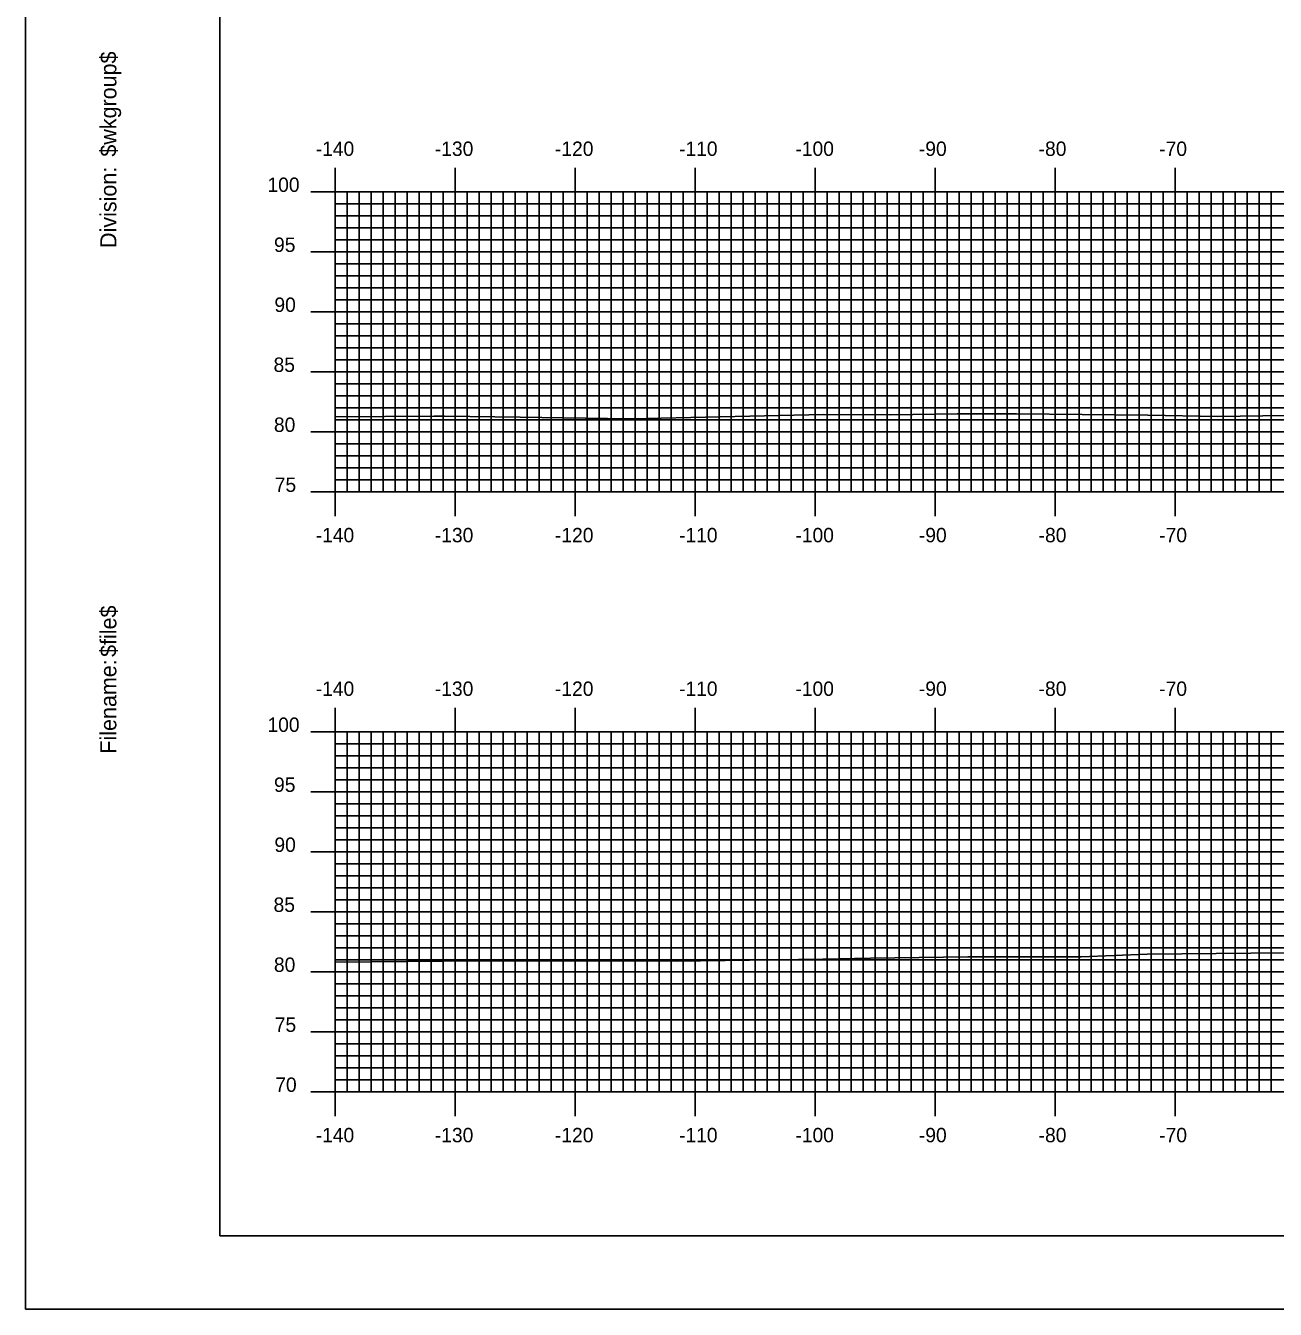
# Model space of a CAD drawing. Extents: x 853723 to 854066, y 364366 to 364586.
# Drawn here: x 853722.9 to 853827.1, y 364365.7 to 364472.6 of the extents above; entities that cross this region are included whole.
import ezdxf

# ---------------------------------------------------------------- set-up
doc = ezdxf.new("R2010")
doc.units = 0
for name, color, linetype in [('BORDER', 7, 'Continuous'), ('H_V ANNOTATION', 7, 'Continuous'), ('MAJOR', 7, 'Continuous'), ('MINOR', 7, 'Continuous'), ('PLOT BOUNDARY', 7, 'Continuous'), ('S_Roadway_Centerline', 7, 'Continuous')]:
    doc.layers.add(name, color=color, linetype=linetype)

msp = doc.modelspace()

# ---------------------------------------------------------------- linework, layer by layer
at = {"layer": 'BORDER'}
msp.add_lwpolyline([(853739.12, 364371.79), (854059.12, 364371.79), (854059.12, 364581.79), (853739.12, 364581.79)], close=True, dxfattribs=at)
at = {"layer": 'MAJOR'}
for p, q in [((853748.72, 364460.79), (853748.72, 364458.79)), ((853758.72, 364460.79), (853758.72, 364458.79)), ((853768.72, 364460.79), (853768.72, 364458.79)), ((853778.72, 364460.79), (853778.72, 364458.79)), ((853788.72, 364460.79), (853788.72, 364458.79)), ((853798.72, 364460.79), (853798.72, 364458.79)), ((853808.72, 364460.79), (853808.72, 364458.79)), ((853818.72, 364460.79), (853818.72, 364458.79)), ((853746.71, 364458.79), (853748.72, 364458.79)), ((853748.72, 364458.79), (854028.72, 364458.79)), ((853748.72, 364433.79), (853748.72, 364458.79)), ((853748.72, 364433.79), (853748.72, 364458.79)), ((853748.72, 364458.79), (854028.72, 364458.79)), ((853758.72, 364433.79), (853758.72, 364458.79)), ((853768.72, 364433.79), (853768.72, 364458.79)), ((853778.72, 364433.79), (853778.72, 364458.79)), ((853788.72, 364433.79), (853788.72, 364458.79)), ((853798.72, 364433.79), (853798.72, 364458.79)), ((853808.72, 364433.79), (853808.72, 364458.79)), ((853818.72, 364433.79), (853818.72, 364458.79)), ((853746.71, 364453.79), (853748.72, 364453.79)), ((853748.72, 364453.79), (854028.72, 364453.79)), ((853746.71, 364448.79), (853748.72, 364448.79)), ((853748.72, 364448.79), (854028.72, 364448.79)), ((853746.71, 364443.79), (853748.72, 364443.79)), ((853748.72, 364443.79), (854028.72, 364443.79)), ((853746.71, 364438.79), (853748.72, 364438.79)), ((853748.72, 364438.79), (854028.72, 364438.79)), ((853746.71, 364433.79), (853748.72, 364433.79)), ((853748.72, 364433.79), (854028.72, 364433.79)), ((853748.72, 364433.79), (854028.72, 364433.79)), ((853748.72, 364431.78), (853748.72, 364433.79)), ((853758.72, 364431.78), (853758.72, 364433.79)), ((853768.72, 364431.78), (853768.72, 364433.79)), ((853778.72, 364431.78), (853778.72, 364433.79)), ((853788.72, 364431.78), (853788.72, 364433.79)), ((853798.72, 364431.78), (853798.72, 364433.79)), ((853808.72, 364431.78), (853808.72, 364433.79)), ((853818.72, 364431.78), (853818.72, 364433.79)), ((853748.72, 364415.79), (853748.72, 364413.79)), ((853758.72, 364415.79), (853758.72, 364413.79)), ((853768.72, 364415.79), (853768.72, 364413.79)), ((853778.72, 364415.79), (853778.72, 364413.79)), ((853788.72, 364415.79), (853788.72, 364413.79)), ((853798.72, 364415.79), (853798.72, 364413.79)), ((853808.72, 364415.79), (853808.72, 364413.79)), ((853818.72, 364415.79), (853818.72, 364413.79)), ((853746.71, 364413.79), (853748.72, 364413.79)), ((853748.72, 364413.79), (854028.72, 364413.79)), ((853748.72, 364383.79), (853748.72, 364413.79)), ((853748.72, 364383.79), (853748.72, 364413.79)), ((853748.72, 364413.79), (854028.72, 364413.79)), ((853758.72, 364383.79), (853758.72, 364413.79)), ((853768.72, 364383.79), (853768.72, 364413.79)), ((853778.72, 364383.79), (853778.72, 364413.79)), ((853788.72, 364383.79), (853788.72, 364413.79)), ((853798.72, 364383.79), (853798.72, 364413.79)), ((853808.72, 364383.79), (853808.72, 364413.79)), ((853818.72, 364383.79), (853818.72, 364413.79)), ((853746.71, 364408.79), (853748.72, 364408.79)), ((853748.72, 364408.79), (854028.72, 364408.79)), ((853746.71, 364403.79), (853748.72, 364403.79)), ((853748.72, 364403.79), (854028.72, 364403.79)), ((853746.71, 364398.79), (853748.72, 364398.79)), ((853748.72, 364398.79), (854028.72, 364398.79)), ((853746.71, 364393.79), (853748.72, 364393.79)), ((853748.72, 364393.79), (854028.72, 364393.79)), ((853746.71, 364388.79), (853748.72, 364388.79)), ((853748.72, 364388.79), (854028.72, 364388.79)), ((853746.71, 364383.79), (853748.72, 364383.79)), ((853748.72, 364383.79), (854028.72, 364383.79)), ((853748.72, 364383.79), (854028.72, 364383.79)), ((853748.72, 364381.78), (853748.72, 364383.79)), ((853758.72, 364381.78), (853758.72, 364383.79)), ((853768.72, 364381.78), (853768.72, 364383.79)), ((853778.72, 364381.78), (853778.72, 364383.79)), ((853788.72, 364381.78), (853788.72, 364383.79)), ((853798.72, 364381.78), (853798.72, 364383.79)), ((853808.72, 364381.78), (853808.72, 364383.79)), ((853818.72, 364381.78), (853818.72, 364383.79))]:
    msp.add_line(p, q, dxfattribs=at)
at = {"layer": 'MINOR'}
for p, q in [((853749.72, 364433.79), (853749.72, 364458.79)), ((853750.72, 364433.79), (853750.72, 364458.79)), ((853751.72, 364433.79), (853751.72, 364458.79)), ((853752.72, 364433.79), (853752.72, 364458.79)), ((853753.72, 364433.79), (853753.72, 364458.79)), ((853754.72, 364433.79), (853754.72, 364458.79)), ((853755.72, 364433.79), (853755.72, 364458.79)), ((853756.72, 364433.79), (853756.72, 364458.79)), ((853757.72, 364433.79), (853757.72, 364458.79)), ((853759.72, 364433.79), (853759.72, 364458.79)), ((853760.72, 364433.79), (853760.72, 364458.79)), ((853761.72, 364433.79), (853761.72, 364458.79)), ((853762.72, 364433.79), (853762.72, 364458.79)), ((853763.72, 364433.79), (853763.72, 364458.79)), ((853764.72, 364433.79), (853764.72, 364458.79)), ((853765.72, 364433.79), (853765.72, 364458.79)), ((853766.72, 364433.79), (853766.72, 364458.79)), ((853767.72, 364433.79), (853767.72, 364458.79)), ((853769.72, 364433.79), (853769.72, 364458.79)), ((853770.72, 364433.79), (853770.72, 364458.79)), ((853771.72, 364433.79), (853771.72, 364458.79)), ((853772.72, 364433.79), (853772.72, 364458.79)), ((853773.72, 364433.79), (853773.72, 364458.79)), ((853774.72, 364433.79), (853774.72, 364458.79)), ((853775.72, 364433.79), (853775.72, 364458.79)), ((853776.72, 364433.79), (853776.72, 364458.79)), ((853777.72, 364433.79), (853777.72, 364458.79)), ((853779.72, 364433.79), (853779.72, 364458.79)), ((853780.72, 364433.79), (853780.72, 364458.79)), ((853781.72, 364433.79), (853781.72, 364458.79)), ((853782.72, 364433.79), (853782.72, 364458.79)), ((853783.72, 364433.79), (853783.72, 364458.79)), ((853784.72, 364433.79), (853784.72, 364458.79)), ((853785.72, 364433.79), (853785.72, 364458.79)), ((853786.72, 364433.79), (853786.72, 364458.79)), ((853787.72, 364433.79), (853787.72, 364458.79)), ((853789.72, 364433.79), (853789.72, 364458.79)), ((853790.72, 364433.79), (853790.72, 364458.79)), ((853791.72, 364433.79), (853791.72, 364458.79)), ((853792.72, 364433.79), (853792.72, 364458.79)), ((853793.72, 364433.79), (853793.72, 364458.79)), ((853794.72, 364433.79), (853794.72, 364458.79)), ((853795.72, 364433.79), (853795.72, 364458.79)), ((853796.72, 364433.79), (853796.72, 364458.79)), ((853797.72, 364433.79), (853797.72, 364458.79)), ((853799.72, 364433.79), (853799.72, 364458.79)), ((853800.72, 364433.79), (853800.72, 364458.79)), ((853801.72, 364433.79), (853801.72, 364458.79)), ((853802.72, 364433.79), (853802.72, 364458.79)), ((853803.72, 364433.79), (853803.72, 364458.79)), ((853804.72, 364433.79), (853804.72, 364458.79)), ((853805.72, 364433.79), (853805.72, 364458.79)), ((853806.72, 364433.79), (853806.72, 364458.79)), ((853807.72, 364433.79), (853807.72, 364458.79)), ((853809.72, 364433.79), (853809.72, 364458.79)), ((853810.72, 364433.79), (853810.72, 364458.79)), ((853811.72, 364433.79), (853811.72, 364458.79)), ((853812.72, 364433.79), (853812.72, 364458.79)), ((853813.72, 364433.79), (853813.72, 364458.79)), ((853814.72, 364433.79), (853814.72, 364458.79)), ((853815.72, 364433.79), (853815.72, 364458.79)), ((853816.72, 364433.79), (853816.72, 364458.79)), ((853817.72, 364433.79), (853817.72, 364458.79)), ((853819.72, 364433.79), (853819.72, 364458.79)), ((853820.72, 364433.79), (853820.72, 364458.79)), ((853821.72, 364433.79), (853821.72, 364458.79)), ((853822.72, 364433.79), (853822.72, 364458.79)), ((853823.72, 364433.79), (853823.72, 364458.79)), ((853824.72, 364433.79), (853824.72, 364458.79)), ((853825.72, 364433.79), (853825.72, 364458.79)), ((853826.72, 364433.79), (853826.72, 364458.79)), ((853748.72, 364457.79), (854028.72, 364457.79)), ((853748.72, 364457.79), (853750.72, 364457.79)), ((853748.72, 364456.79), (854028.72, 364456.79)), ((853748.72, 364456.79), (853750.72, 364456.79)), ((853748.72, 364455.79), (854028.72, 364455.79)), ((853748.72, 364455.79), (853750.72, 364455.79)), ((853748.72, 364454.79), (854028.72, 364454.79)), ((853748.72, 364454.79), (853750.72, 364454.79)), ((853748.72, 364452.79), (854028.72, 364452.79)), ((853748.72, 364452.79), (853750.72, 364452.79)), ((853748.72, 364451.79), (854028.72, 364451.79)), ((853748.72, 364451.79), (853750.72, 364451.79)), ((853748.72, 364450.79), (854028.72, 364450.79)), ((853748.72, 364450.79), (853750.72, 364450.79)), ((853748.72, 364449.79), (854028.72, 364449.79)), ((853748.72, 364449.79), (853750.72, 364449.79)), ((853748.72, 364447.79), (854028.72, 364447.79)), ((853748.72, 364447.79), (853750.72, 364447.79)), ((853748.72, 364446.79), (854028.72, 364446.79)), ((853748.72, 364446.79), (853750.72, 364446.79)), ((853748.72, 364445.79), (854028.72, 364445.79)), ((853748.72, 364445.79), (853750.72, 364445.79)), ((853748.72, 364444.79), (854028.72, 364444.79)), ((853748.72, 364444.79), (853750.72, 364444.79)), ((853748.72, 364442.79), (854028.72, 364442.79)), ((853748.72, 364442.79), (853750.72, 364442.79)), ((853748.72, 364441.79), (854028.72, 364441.79)), ((853748.72, 364441.79), (853750.72, 364441.79)), ((853748.72, 364440.79), (854028.72, 364440.79)), ((853748.72, 364440.79), (853750.72, 364440.79)), ((853748.72, 364439.79), (854028.72, 364439.79)), ((853748.72, 364439.79), (853750.72, 364439.79)), ((853748.72, 364437.79), (854028.72, 364437.79)), ((853748.72, 364437.79), (853750.72, 364437.79)), ((853748.72, 364436.79), (854028.72, 364436.79)), ((853748.72, 364436.79), (853750.72, 364436.79)), ((853748.72, 364435.79), (854028.72, 364435.79)), ((853748.72, 364435.79), (853750.72, 364435.79)), ((853748.72, 364434.79), (854028.72, 364434.79)), ((853748.72, 364434.79), (853750.72, 364434.79)), ((853749.72, 364383.79), (853749.72, 364413.79)), ((853750.72, 364383.79), (853750.72, 364413.79)), ((853751.72, 364383.79), (853751.72, 364413.79)), ((853752.72, 364383.79), (853752.72, 364413.79)), ((853753.72, 364383.79), (853753.72, 364413.79)), ((853754.72, 364383.79), (853754.72, 364413.79)), ((853755.72, 364383.79), (853755.72, 364413.79)), ((853756.72, 364383.79), (853756.72, 364413.79)), ((853757.72, 364383.79), (853757.72, 364413.79)), ((853759.72, 364383.79), (853759.72, 364413.79)), ((853760.72, 364383.79), (853760.72, 364413.79)), ((853761.72, 364383.79), (853761.72, 364413.79)), ((853762.72, 364383.79), (853762.72, 364413.79)), ((853763.72, 364383.79), (853763.72, 364413.79)), ((853764.72, 364383.79), (853764.72, 364413.79)), ((853765.72, 364383.79), (853765.72, 364413.79)), ((853766.72, 364383.79), (853766.72, 364413.79)), ((853767.72, 364383.79), (853767.72, 364413.79)), ((853769.72, 364383.79), (853769.72, 364413.79)), ((853770.72, 364383.79), (853770.72, 364413.79)), ((853771.72, 364383.79), (853771.72, 364413.79)), ((853772.72, 364383.79), (853772.72, 364413.79)), ((853773.72, 364383.79), (853773.72, 364413.79)), ((853774.72, 364383.79), (853774.72, 364413.79)), ((853775.72, 364383.79), (853775.72, 364413.79)), ((853776.72, 364383.79), (853776.72, 364413.79)), ((853777.72, 364383.79), (853777.72, 364413.79)), ((853779.72, 364383.79), (853779.72, 364413.79)), ((853780.72, 364383.79), (853780.72, 364413.79)), ((853781.72, 364383.79), (853781.72, 364413.79)), ((853782.72, 364383.79), (853782.72, 364413.79)), ((853783.72, 364383.79), (853783.72, 364413.79)), ((853784.72, 364383.79), (853784.72, 364413.79)), ((853785.72, 364383.79), (853785.72, 364413.79)), ((853786.72, 364383.79), (853786.72, 364413.79)), ((853787.72, 364383.79), (853787.72, 364413.79)), ((853789.72, 364383.79), (853789.72, 364413.79)), ((853790.72, 364383.79), (853790.72, 364413.79)), ((853791.72, 364383.79), (853791.72, 364413.79)), ((853792.72, 364383.79), (853792.72, 364413.79)), ((853793.72, 364383.79), (853793.72, 364413.79)), ((853794.72, 364383.79), (853794.72, 364413.79)), ((853795.72, 364383.79), (853795.72, 364413.79)), ((853796.72, 364383.79), (853796.72, 364413.79)), ((853797.72, 364383.79), (853797.72, 364413.79)), ((853799.72, 364383.79), (853799.72, 364413.79)), ((853800.72, 364383.79), (853800.72, 364413.79)), ((853801.72, 364383.79), (853801.72, 364413.79)), ((853802.72, 364383.79), (853802.72, 364413.79)), ((853803.72, 364383.79), (853803.72, 364413.79)), ((853804.72, 364383.79), (853804.72, 364413.79)), ((853805.72, 364383.79), (853805.72, 364413.79)), ((853806.72, 364383.79), (853806.72, 364413.79)), ((853807.72, 364383.79), (853807.72, 364413.79)), ((853809.72, 364383.79), (853809.72, 364413.79)), ((853810.72, 364383.79), (853810.72, 364413.79)), ((853811.72, 364383.79), (853811.72, 364413.79)), ((853812.72, 364383.79), (853812.72, 364413.79)), ((853813.72, 364383.79), (853813.72, 364413.79)), ((853814.72, 364383.79), (853814.72, 364413.79)), ((853815.72, 364383.79), (853815.72, 364413.79)), ((853816.72, 364383.79), (853816.72, 364413.79)), ((853817.72, 364383.79), (853817.72, 364413.79)), ((853819.72, 364383.79), (853819.72, 364413.79)), ((853820.72, 364383.79), (853820.72, 364413.79)), ((853821.72, 364383.79), (853821.72, 364413.79)), ((853822.72, 364383.79), (853822.72, 364413.79)), ((853823.72, 364383.79), (853823.72, 364413.79)), ((853824.72, 364383.79), (853824.72, 364413.79)), ((853825.72, 364383.79), (853825.72, 364413.79)), ((853826.72, 364383.79), (853826.72, 364413.79)), ((853748.72, 364412.79), (854028.72, 364412.79)), ((853748.72, 364412.79), (853750.72, 364412.79)), ((853748.72, 364411.79), (854028.72, 364411.79)), ((853748.72, 364411.79), (853750.72, 364411.79)), ((853748.72, 364410.79), (854028.72, 364410.79)), ((853748.72, 364410.79), (853750.72, 364410.79)), ((853748.72, 364409.79), (854028.72, 364409.79)), ((853748.72, 364409.79), (853750.72, 364409.79)), ((853748.72, 364407.79), (854028.72, 364407.79)), ((853748.72, 364407.79), (853750.72, 364407.79)), ((853748.72, 364406.79), (854028.72, 364406.79)), ((853748.72, 364406.79), (853750.72, 364406.79)), ((853748.72, 364405.79), (854028.72, 364405.79)), ((853748.72, 364405.79), (853750.72, 364405.79)), ((853748.72, 364404.79), (854028.72, 364404.79)), ((853748.72, 364404.79), (853750.72, 364404.79)), ((853748.72, 364402.79), (854028.72, 364402.79)), ((853748.72, 364402.79), (853750.72, 364402.79)), ((853748.72, 364401.79), (854028.72, 364401.79)), ((853748.72, 364401.79), (853750.72, 364401.79)), ((853748.72, 364400.79), (854028.72, 364400.79)), ((853748.72, 364400.79), (853750.72, 364400.79)), ((853748.72, 364399.79), (854028.72, 364399.79)), ((853748.72, 364399.79), (853750.72, 364399.79)), ((853748.72, 364397.79), (854028.72, 364397.79)), ((853748.72, 364397.79), (853750.72, 364397.79)), ((853748.72, 364396.79), (854028.72, 364396.79)), ((853748.72, 364396.79), (853750.72, 364396.79)), ((853748.72, 364395.79), (854028.72, 364395.79)), ((853748.72, 364395.79), (853750.72, 364395.79)), ((853748.72, 364394.79), (854028.72, 364394.79)), ((853748.72, 364394.79), (853750.72, 364394.79)), ((853748.72, 364392.79), (854028.72, 364392.79)), ((853748.72, 364392.79), (853750.72, 364392.79)), ((853748.72, 364391.79), (854028.72, 364391.79)), ((853748.72, 364391.79), (853750.72, 364391.79)), ((853748.72, 364390.79), (854028.72, 364390.79)), ((853748.72, 364390.79), (853750.72, 364390.79)), ((853748.72, 364389.79), (854028.72, 364389.79)), ((853748.72, 364389.79), (853750.72, 364389.79)), ((853748.72, 364387.79), (854028.72, 364387.79)), ((853748.72, 364387.79), (853750.72, 364387.79)), ((853748.72, 364386.79), (854028.72, 364386.79)), ((853748.72, 364386.79), (853750.72, 364386.79)), ((853748.72, 364385.79), (854028.72, 364385.79)), ((853748.72, 364385.79), (853750.72, 364385.79)), ((853748.72, 364384.79), (854028.72, 364384.79)), ((853748.72, 364384.79), (853750.72, 364384.79))]:
    msp.add_line(p, q, dxfattribs=at)
at = {"layer": 'PLOT BOUNDARY'}
msp.add_lwpolyline([(853722.93, 364365.67), (854062.93, 364365.67), (854062.93, 364585.67), (853722.93, 364585.67)], close=True, dxfattribs=at)
at = {"layer": 'S_Roadway_Centerline'}
for points in [[(853748.72, 364440.05), (853756.97, 364440.09), (853757.83, 364440.1), (853764.13, 364440.02), (853773.23, 364439.89), (853774.66, 364439.92), (853789.42, 364440.23), (853795.01, 364440.22), (853800.56, 364440.3), (853805.5, 364440.29), (853816.45, 364440.19), (853822.25, 364440.08), (853831.74, 364440.22)], [(853748.72, 364394.6), (853760.71, 364394.72), (853768.68, 364394.72), (853777.15, 364394.69), (853789.37, 364394.86), (853793.33, 364394.92), (853801.44, 364395.04), (853810.89, 364395.05), (853816.39, 364395.26), (853833.68, 364395.44), (853840.88, 364395.6), (853844.96, 364395.68), (853845.88, 364395.69), (853849.46, 364395.62), (853862.69, 364395.31), (853869.61, 364395.32), (853879.11, 364395.2), (853883.39, 364395.34), (853902.78, 364395.79), (853910.05, 364395.81), (853913.72, 364395.8), (853923.38, 364395.33), (853930.43, 364395), (853940.64, 364395.08)]]:
    msp.add_lwpolyline(points, dxfattribs=at)

# ---------------------------------------------------------------- texts
at = {"layer": 'BORDER'}
for s, p in [('$wkgroup$', (853730.49, 364461.73)), ('Division:', (853730.49, 364454.12)), ('$file$', (853730.49, 364420.04)), ('Filename:', (853730.49, 364411.98))]:
    msp.add_text(s, height=1.339, rotation=90, dxfattribs=at).set_placement(p)
at = {"layer": 'H_V ANNOTATION'}
for s, p in [('-140', (853747.1, 364461.79)), ('-130', (853757.03, 364461.79)), ('-120', (853767.04, 364461.79)), ('-110', (853777.38, 364461.79)), ('-100', (853787.08, 364461.79)), ('-90', (853797.37, 364461.79)), ('-80', (853807.35, 364461.79)), ('-70', (853817.4, 364461.79)), ('100', (853743.08, 364458.79)), ('95', (853743.63, 364453.79)), ('90', (853743.66, 364448.79)), ('85', (853743.59, 364443.79)), ('80', (853743.62, 364438.79)), ('75', (853743.69, 364433.79)), ('-140', (853747.1, 364429.59)), ('-130', (853757.03, 364429.59)), ('-120', (853767.04, 364429.59)), ('-110', (853777.38, 364429.59)), ('-100', (853787.08, 364429.59)), ('-90', (853797.37, 364429.59)), ('-80', (853807.35, 364429.59)), ('-70', (853817.4, 364429.59)), ('-140', (853747.1, 364416.79)), ('-130', (853757.03, 364416.79)), ('-120', (853767.04, 364416.79)), ('-110', (853777.38, 364416.79)), ('-100', (853787.08, 364416.79)), ('-90', (853797.37, 364416.79)), ('-80', (853807.35, 364416.79)), ('-70', (853817.4, 364416.79)), ('100', (853743.08, 364413.79)), ('95', (853743.63, 364408.79)), ('90', (853743.66, 364403.79)), ('85', (853743.59, 364398.79)), ('80', (853743.62, 364393.79)), ('75', (853743.69, 364388.79)), ('70', (853743.73, 364383.79)), ('-140', (853747.1, 364379.59)), ('-130', (853757.03, 364379.59)), ('-120', (853767.04, 364379.59)), ('-110', (853777.38, 364379.59)), ('-100', (853787.08, 364379.59)), ('-90', (853797.37, 364379.59)), ('-80', (853807.35, 364379.59)), ('-70', (853817.4, 364379.59))]:
    msp.add_text(s, height=1.2, dxfattribs=at).set_placement(p)
at = {"layer": 'MAJOR'}
for p in [(853748.71, 364433.79), (853748.71, 364383.79)]:
    msp.add_text('-', height=0.012, dxfattribs=at).set_placement(p)

doc.saveas('drawing.dxf')
